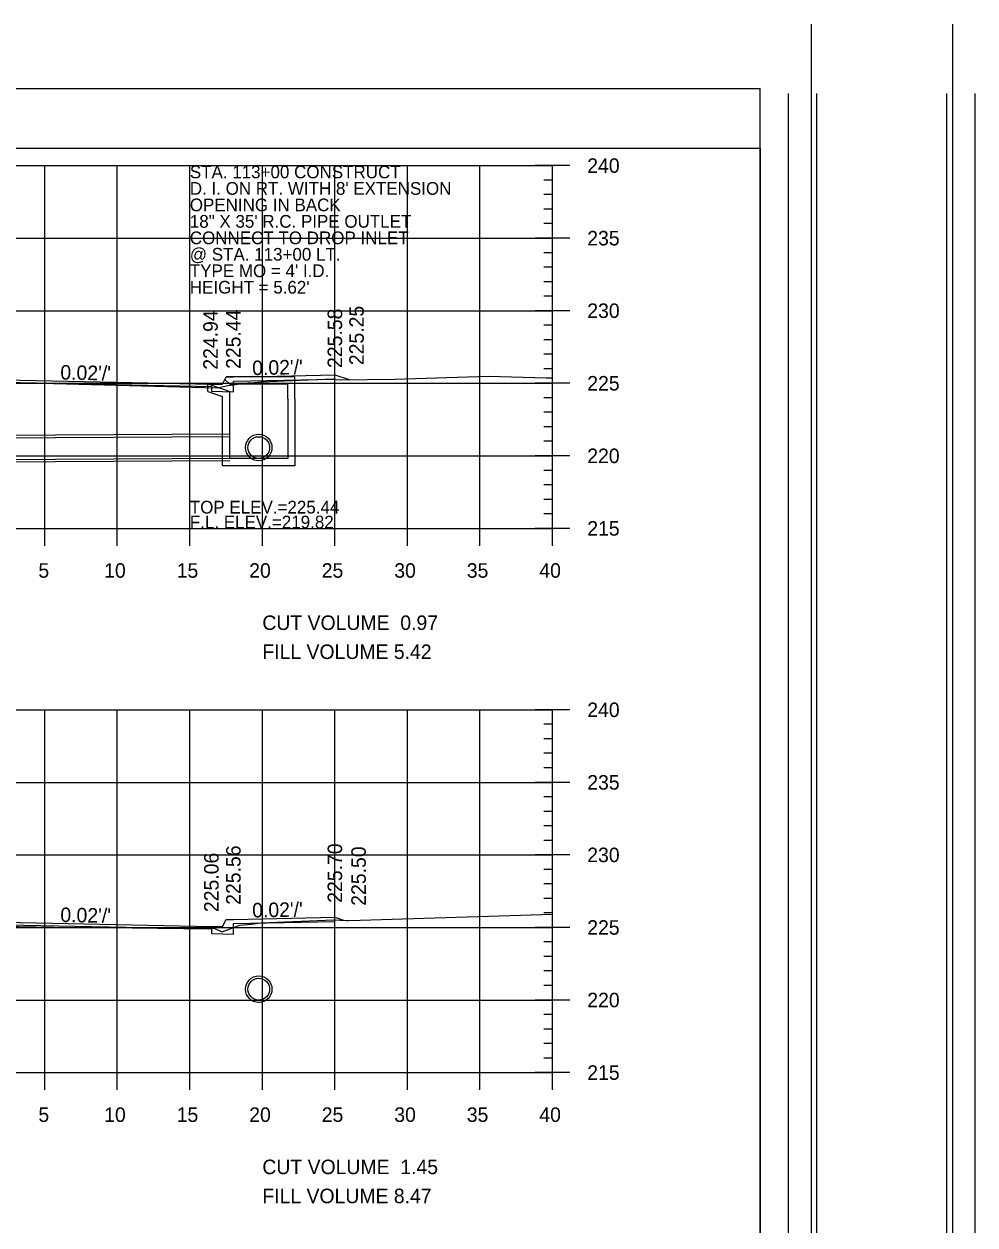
# Model space of a CAD drawing. Extents: x 1367903 to 1373764, y 376865 to 382130.
# Drawn here: x 1373178.8 to 1373310, y 377454.8 to 377620.4 of the extents above; entities that cross this region are included whole.
import ezdxf

# ---------------------------------------------------------------- set-up
doc = ezdxf.new("R2010")
doc.units = 0
for name, color, linetype in [('R_Axis', 7, 'Continuous'), ('R_Axis Annot', 7, 'Continuous'), ('R_Border', 7, 'Continuous'), ('R_Border PE', 7, 'Continuous'), ('R_Draft', 7, 'Continuous'), ('R_Exist Surface', 7, 'Continuous'), ('R_Fin Surface', 7, 'Continuous'), ('R_Fin Surface Annot', 7, 'Continuous'), ('R_Grid', 7, 'Continuous'), ('R_Water', 7, 'Continuous'), ('R_Water Annot', 7, 'Continuous')]:
    doc.layers.add(name, color=color, linetype=linetype)

msp = doc.modelspace()

# ---------------------------------------------------------------- linework, layer by layer
for p, q in [((1373204.19, 377570.75), (1373207.19, 377569.71)), ((1373206.52, 377571.38), (1373206.69, 377571.71)), ((1373206.52, 377571.38), (1373207.19, 377570.71)), ((1373216.19, 377571.71), (1373206.69, 377571.71)), ((1373216.19, 377568.71), (1373216.19, 377571.71)), ((1373204.19, 377569.69), (1373206.19, 377569)), ((1373215.19, 377570.71), (1373207.19, 377570.71)), ((1373207.19, 377568.71), (1373207.19, 377569.71)), ((1373215.19, 377568.71), (1373215.19, 377570.71)), ((1373206.19, 377568.71), (1373206.19, 377569))]:
    msp.add_line(p, q)
for points in [[(1373135.69, 377571.71), (1373135.69, 377571.04), (1373135.69, 377571.04), (1373135.69, 377569.68), (1373138.69, 377569.74), (1373138.69, 377570.41), (1373171.69, 377571.07), (1373204.69, 377570.41), (1373204.69, 377569.74), (1373207.69, 377569.68), (1373207.69, 377571.12), (1373221.69, 377571.4), (1373221.69, 377571.99)], [(1373204.19, 377569.69), (1373204.19, 377570.75)], [(1373135.69, 377496.96), (1373135.69, 377496.29), (1373135.69, 377496.29), (1373135.69, 377494.93), (1373138.69, 377494.99), (1373138.69, 377495.65), (1373171.69, 377496.31), (1373204.69, 377495.65), (1373204.69, 377494.99), (1373207.69, 377494.93), (1373207.69, 377496.37), (1373221.69, 377496.65), (1373221.69, 377497.24)]]:
    msp.add_lwpolyline(points)
at = {"layer": 'R_Axis'}
for p, q in [((1373254.09, 377600.84), (1373249.29, 377600.84)), ((1373251.69, 377550.84), (1373251.69, 377600.84)), ((1373251.69, 377598.84), (1373250.49, 377598.84)), ((1373251.69, 377596.84), (1373250.49, 377596.84)), ((1373251.69, 377594.84), (1373250.49, 377594.84)), ((1373251.69, 377592.84), (1373250.49, 377592.84)), ((1373254.09, 377590.84), (1373249.29, 377590.84)), ((1373251.69, 377588.84), (1373250.49, 377588.84)), ((1373251.69, 377586.84), (1373250.49, 377586.84)), ((1373251.69, 377584.84), (1373250.49, 377584.84)), ((1373251.69, 377582.84), (1373250.49, 377582.84)), ((1373254.09, 377580.84), (1373249.29, 377580.84)), ((1373251.69, 377578.84), (1373250.49, 377578.84)), ((1373251.69, 377576.84), (1373250.49, 377576.84)), ((1373251.69, 377574.84), (1373250.49, 377574.84)), ((1373251.69, 377572.84), (1373250.49, 377572.84)), ((1373254.09, 377570.84), (1373249.29, 377570.84)), ((1373251.69, 377568.84), (1373250.49, 377568.84)), ((1373251.69, 377566.84), (1373250.49, 377566.84)), ((1373251.69, 377564.84), (1373250.49, 377564.84)), ((1373251.69, 377562.84), (1373250.49, 377562.84)), ((1373254.09, 377560.84), (1373249.29, 377560.84)), ((1373251.69, 377558.84), (1373250.49, 377558.84)), ((1373251.69, 377556.84), (1373250.49, 377556.84)), ((1373251.69, 377554.84), (1373250.49, 377554.84)), ((1373181.69, 377548.44), (1373181.69, 377553.24)), ((1373191.69, 377548.44), (1373191.69, 377553.24)), ((1373201.69, 377548.44), (1373201.69, 377553.24)), ((1373211.69, 377548.44), (1373211.69, 377553.24)), ((1373221.69, 377548.44), (1373221.69, 377553.24)), ((1373231.69, 377548.44), (1373231.69, 377553.24)), ((1373241.69, 377548.44), (1373241.69, 377553.24)), ((1373251.69, 377552.84), (1373250.49, 377552.84)), ((1373251.69, 377548.44), (1373251.69, 377553.24)), ((1373091.69, 377550.84), (1373251.69, 377550.84)), ((1373254.09, 377550.84), (1373249.29, 377550.84)), ((1373254.09, 377525.84), (1373249.29, 377525.84)), ((1373251.69, 377475.84), (1373251.69, 377525.84)), ((1373251.69, 377523.84), (1373250.49, 377523.84)), ((1373251.69, 377521.84), (1373250.49, 377521.84)), ((1373251.69, 377519.84), (1373250.49, 377519.84)), ((1373251.69, 377517.84), (1373250.49, 377517.84)), ((1373254.09, 377515.84), (1373249.29, 377515.84)), ((1373251.69, 377513.84), (1373250.49, 377513.84)), ((1373251.69, 377511.84), (1373250.49, 377511.84)), ((1373251.69, 377509.84), (1373250.49, 377509.84)), ((1373251.69, 377507.84), (1373250.49, 377507.84)), ((1373254.09, 377505.84), (1373249.29, 377505.84)), ((1373251.69, 377503.84), (1373250.49, 377503.84)), ((1373251.69, 377501.84), (1373250.49, 377501.84)), ((1373251.69, 377499.84), (1373250.49, 377499.84)), ((1373251.69, 377497.84), (1373250.49, 377497.84)), ((1373254.09, 377495.84), (1373249.29, 377495.84)), ((1373251.69, 377493.84), (1373250.49, 377493.84)), ((1373251.69, 377491.84), (1373250.49, 377491.84)), ((1373251.69, 377489.84), (1373250.49, 377489.84)), ((1373251.69, 377487.84), (1373250.49, 377487.84)), ((1373254.09, 377485.84), (1373249.29, 377485.84)), ((1373251.69, 377483.84), (1373250.49, 377483.84)), ((1373251.69, 377481.84), (1373250.49, 377481.84)), ((1373251.69, 377479.84), (1373250.49, 377479.84)), ((1373181.69, 377473.44), (1373181.69, 377478.24)), ((1373191.69, 377473.44), (1373191.69, 377478.24)), ((1373201.69, 377473.44), (1373201.69, 377478.24)), ((1373211.69, 377473.44), (1373211.69, 377478.24)), ((1373221.69, 377473.44), (1373221.69, 377478.24)), ((1373231.69, 377473.44), (1373231.69, 377478.24)), ((1373241.69, 377473.44), (1373241.69, 377478.24)), ((1373251.69, 377473.44), (1373251.69, 377478.24)), ((1373251.69, 377477.84), (1373250.49, 377477.84)), ((1373091.69, 377475.84), (1373251.69, 377475.84)), ((1373254.09, 377475.84), (1373249.29, 377475.84))]:
    msp.add_line(p, q, dxfattribs=at)
at = {"layer": 'R_Border'}
for p, q in [((1373287.35, 377620.35), (1373287.35, 377279.12)), ((1373306.84, 377620.35), (1373306.84, 377279.12)), ((1373075.99, 377611.47), (1373280.31, 377611.47)), ((1373280.31, 377280.59), (1373280.31, 377611.47))]:
    msp.add_line(p, q, dxfattribs=at)
at = {"layer": 'R_Border PE'}
for p, q in [((1373284.24, 377288.8), (1373284.24, 377610.76)), ((1373288.15, 377288.8), (1373288.15, 377610.76)), ((1373306.04, 377610.76), (1373306.04, 377288.8)), ((1373309.95, 377610.76), (1373309.95, 377288.8)), ((1373075.99, 377603.25), (1373280.31, 377603.25)), ((1373280.31, 377603.25), (1373280.31, 377288.8))]:
    msp.add_line(p, q, dxfattribs=at)
at = {"layer": 'R_Exist Surface'}
for points in [[(1373171.39, 377571.04), (1373181.18, 377570.85), (1373205.51, 377570.23), (1373206.93, 377570.52), (1373209.62, 377570.89), (1373210.08, 377570.89), (1373211.53, 377571.04), (1373216.89, 377571.28), (1373221.52, 377571.47), (1373221.84, 377571.37), (1373222.42, 377571.32), (1373229.97, 377571.4), (1373242.85, 377571.84), (1373250.83, 377571.58), (1373251.69, 377571.58)], [(1373170.82, 377496.12), (1373185.33, 377495.85), (1373190.25, 377495.83), (1373204.33, 377495.65), (1373204.99, 377495.72), (1373206.16, 377495.25), (1373208.58, 377496.17), (1373210.18, 377496.31), (1373211.47, 377496.49), (1373214.81, 377496.62), (1373221.52, 377496.9), (1373223.28, 377496.81), (1373223.52, 377496.82), (1373225.18, 377496.86), (1373251.69, 377497.67)]]:
    msp.add_lwpolyline(points, dxfattribs=at)
at = {"layer": 'R_Fin Surface'}
for points in [[(1373130.78, 377570.07), (1373135.69, 377571.71), (1373136.69, 377571.71), (1373137.19, 377570.71), (1373138.69, 377570.74), (1373160.69, 377571.18), (1373171.69, 377571.4), (1373182.69, 377571.18), (1373204.69, 377570.74), (1373206.19, 377570.71), (1373206.69, 377571.71), (1373207.69, 377571.71), (1373211.69, 377571.79), (1373221.69, 377571.99), (1373223.65, 377571.34)], [(1373130.76, 377495.31), (1373135.69, 377496.96), (1373136.69, 377496.96), (1373137.19, 377495.96), (1373138.69, 377495.99), (1373160.69, 377496.43), (1373171.69, 377496.65), (1373182.69, 377496.43), (1373204.69, 377495.99), (1373206.19, 377495.96), (1373206.69, 377496.96), (1373207.69, 377496.96), (1373211.69, 377497.04), (1373221.69, 377497.24), (1373222.9, 377496.83)]]:
    msp.add_lwpolyline(points, dxfattribs=at)
at = {"layer": 'R_Grid'}
for p, q in [((1373091.69, 377600.84), (1373251.69, 377600.84)), ((1373181.69, 377550.84), (1373181.69, 377600.84)), ((1373191.69, 377550.84), (1373191.69, 377600.84)), ((1373201.69, 377550.84), (1373201.69, 377600.84)), ((1373211.69, 377550.84), (1373211.69, 377600.84)), ((1373221.69, 377550.84), (1373221.69, 377600.84)), ((1373231.69, 377550.84), (1373231.69, 377600.84)), ((1373241.69, 377550.84), (1373241.69, 377600.84)), ((1373251.69, 377550.84), (1373251.69, 377600.84)), ((1373091.69, 377590.84), (1373251.69, 377590.84)), ((1373091.69, 377580.84), (1373251.69, 377580.84)), ((1373091.69, 377570.84), (1373251.69, 377570.84)), ((1373091.69, 377560.84), (1373251.69, 377560.84)), ((1373091.69, 377550.84), (1373251.69, 377550.84)), ((1373091.69, 377525.84), (1373251.69, 377525.84)), ((1373181.69, 377475.84), (1373181.69, 377525.84)), ((1373191.69, 377475.84), (1373191.69, 377525.84)), ((1373201.69, 377475.84), (1373201.69, 377525.84)), ((1373211.69, 377475.84), (1373211.69, 377525.84)), ((1373221.69, 377475.84), (1373221.69, 377525.84)), ((1373231.69, 377475.84), (1373231.69, 377525.84)), ((1373241.69, 377475.84), (1373241.69, 377525.84)), ((1373251.69, 377475.84), (1373251.69, 377525.84)), ((1373091.69, 377515.84), (1373251.69, 377515.84)), ((1373091.69, 377505.84), (1373251.69, 377505.84)), ((1373091.69, 377495.84), (1373251.69, 377495.84)), ((1373091.69, 377485.84), (1373251.69, 377485.84)), ((1373091.69, 377475.84), (1373251.69, 377475.84))]:
    msp.add_line(p, q, dxfattribs=at)
at = {"layer": 'R_Water'}
for p, q in [((1373207.19, 377563.82), (1373136.7, 377563.39)), ((1373207.19, 377563.48), (1373136.7, 377563.06)), ((1373211.19, 377563.81), (1373211.19, 377563.81)), ((1373211.19, 377563.48), (1373211.19, 377563.48)), ((1373207.19, 377560.48), (1373136.7, 377560.06)), ((1373207.19, 377560.15), (1373136.7, 377559.73)), ((1373211.19, 377560.48), (1373211.19, 377560.48)), ((1373211.19, 377560.15), (1373211.19, 377560.14)), ((1373211.19, 377489.18), (1373211.19, 377489.13)), ((1373211.19, 377488.85), (1373211.19, 377488.8)), ((1373211.19, 377485.85), (1373211.19, 377485.8)), ((1373211.19, 377485.52), (1373211.19, 377485.47))]:
    msp.add_line(p, q, dxfattribs=at)
for points in [[(1373216.19, 377568.71), (1373216.19, 377559.48), (1373211.19, 377559.48), (1373206.19, 377559.48), (1373206.19, 377568.71)], [(1373215.19, 377568.71), (1373215.19, 377560.48), (1373211.19, 377560.48), (1373207.19, 377560.48), (1373207.19, 377568.71)]]:
    msp.add_lwpolyline(points, dxfattribs=at)
for centre, radius in [((1373211.19, 377561.98), 1.83), ((1373211.19, 377561.98), 1.83), ((1373211.19, 377561.98), 1.5), ((1373211.19, 377561.98), 1.5), ((1373211.19, 377487.33), 1.83), ((1373211.19, 377487.33), 1.5)]:
    msp.add_circle(centre, radius, dxfattribs=at)

# ---------------------------------------------------------------- texts
at = {"layer": 'R_Axis Annot'}
for s, p in [('240', (1373256.49, 377599.84)), ('235', (1373256.49, 377589.84)), ('230', (1373256.49, 377579.84)), ('225', (1373256.49, 377569.84)), ('220', (1373256.49, 377559.84)), ('215', (1373256.49, 377549.84)), ('5', (1373180.81, 377544.04)), ('10', (1373189.88, 377544.04)), ('15', (1373199.88, 377544.04)), ('20', (1373209.88, 377544.04)), ('25', (1373219.88, 377544.04)), ('30', (1373229.88, 377544.04)), ('35', (1373239.88, 377544.04)), ('40', (1373249.88, 377544.04)), ('CUT VOLUME  0.97', (1373211.69, 377536.84)), ('FILL VOLUME 5.42', (1373211.69, 377532.84)), ('240', (1373256.49, 377524.84)), ('235', (1373256.49, 377514.84)), ('230', (1373256.49, 377504.84)), ('225', (1373256.49, 377494.84)), ('220', (1373256.49, 377484.84)), ('215', (1373256.49, 377474.84)), ('5', (1373180.81, 377469.04)), ('10', (1373189.88, 377469.04)), ('15', (1373199.88, 377469.04)), ('20', (1373209.88, 377469.04)), ('25', (1373219.88, 377469.04)), ('30', (1373229.88, 377469.04)), ('35', (1373239.88, 377469.04)), ('40', (1373249.88, 377469.04)), ('CUT VOLUME  1.45', (1373211.69, 377461.84)), ('FILL VOLUME 8.47', (1373211.69, 377457.84))]:
    msp.add_text(s, height=2, dxfattribs=at).set_placement(p)
at = {"layer": 'R_Draft'}
for s, p in [('STA. 113+00 CONSTRUCT', (1373201.69, 377599.09)), ("D. I. ON RT. WITH 8' EXTENSION", (1373201.69, 377596.82)), ('OPENING IN BACK', (1373201.69, 377594.55)), ('18" X 35\' R.C. PIPE OUTLET', (1373201.69, 377592.28)), ('CONNECT TO DROP INLET', (1373201.69, 377590.01)), ('@ STA. 113+00 LT.', (1373201.69, 377587.74)), ("TYPE MO = 4' I.D.", (1373201.69, 377585.47)), ("HEIGHT = 5.62'", (1373201.69, 377583.2))]:
    msp.add_text(s, height=1.75, dxfattribs=at).set_placement(p)
at = {"layer": 'R_Fin Surface Annot'}
for s, rotation, p in [('224.94', 90, (1373205.54, 377572.71)), ('225.44', 90, (1373208.69, 377572.82)), ('225.58', 90, (1373222.69, 377572.95)), ('225.25', 90, (1373225.68, 377573.34)), ("0.02'/'", 1.1458, (1373210.31, 377571.96)), ("0.02'/'", 358.8542, (1373183.82, 377571.36)), ('225.56', 90, (1373208.69, 377498.96)), ('225.70', 90, (1373222.69, 377499.24)), ('225.50', 90, (1373225.96, 377498.83)), ('225.06', 90, (1373205.66, 377497.96)), ("0.02'/'", 358.8542, (1373183.82, 377496.6)), ("0.02'/'", 1.1458, (1373210.31, 377497.21))]:
    msp.add_text(s, height=2, rotation=rotation, dxfattribs=at).set_placement(p)
at = {"layer": 'R_Water Annot'}
for s, p in [('TOP ELEV.=225.44', (1373201.69, 377552.89)), ('F.L. ELEV.=219.82', (1373201.69, 377550.84))]:
    msp.add_text(s, height=1.75, dxfattribs=at).set_placement(p)

doc.saveas('drawing.dxf')
